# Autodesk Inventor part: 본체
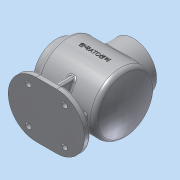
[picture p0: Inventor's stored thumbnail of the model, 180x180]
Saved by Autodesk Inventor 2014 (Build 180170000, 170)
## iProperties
Created: 2023-01
Part Number: 본체
Material: 알루미늄 6061
Document SubType Name: Modeling
Designer: dg
Mass: 1037.87 g
Surface Area: 1159.88 cm^2
Volume: 382.978 cm^3
Density: 2.71 g/cm^3
Appearance: 알루미늄 - 평지
Author: dg
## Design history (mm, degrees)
sketch "스케치1"
  geometry: L1 (0, 0)-(-122, 0); L2 (-122, 0)-(-122, 38); L3 (-122, 38)-(-110, 38); L4 (-110, 38)-(-110, 50); L5 (-110, 50)-(-10.913, 50); A1 r 120 centre (-120, 0) between (0, 0) and (-10.913, 50)
  constraints: 10 end point, 2 perpendicular, 2 point on circle, 1 centre point, 1 horizontal, 1 horizontal alignment, 1 parallel, 1 vertical
  dimensions: "d0" = 120 radius of A1; "d1" = 122 distance of L1.start L1.end; "d9" = 110 horizontal distance of L1.start L4.end; "d10" = 100 diameter of L5 L1; "d11" = 76 diameter of L3 L1
revolve "회전1" sketch "스케치1" stored, may be unused: angle "d3" = 90 deg
node "작업 평면2"
sketch "스케치4"
  geometry: L1 (-122, 38)-(-110, 38) reference; L2 (-122, -38)-(-122, 38) reference; L3 (-122, 0)-(0, 0); L4 (-110, 50)-(-10.913, 50) reference; L5 (-122, 0)-(-122, 27); L6 (-122, 27)-(-105, 27); L7 (-105, 27)-(-105, 45); L8 (-105, 45)-(-14.17, 45); A1 r 120 centre (-120, 0) between (-10.913, -50) and (-10.913, 50) reference; A2 r 115 centre (-120, 0) between (-5, 0) and (-14.17, 45); 2 further points
  constraints: 10 end point, 3 point on circle, 2 midpoint, 2 parallel, 2 perpendicular, 1 centre point, 1 coincident, 1 horizontal, 1 point on line
  dimensions: "d12" = 54 diameter of L6 L3; "d13" = 90 diameter of L8 L3; "d14" = 5 radial gap between concentric circles of A1 A2; "d15" = 17 distance of L5.end L6.end
revolve "회전2" sketch "스케치4" stored, may be unused: angle "d16" = 90 deg
fillet "모깎기1" dims "d19" = 8
fillet "모깎기2" dims "d20" = 3
node "작업 평면5"
node "작업 평면6"
sketch "스케치7"
  geometry: L1 (110, 42)-(110, -42) reference; C1 r 38 at (59, 0); 1 further point
  constraints: 1 centre point, 1 horizontal alignment
  dimensions: "d23" = 51 distance from line of C1.centre L1; "d24" = 76 diameter of C1
extrude "돌출2" join sketch "스케치7" stored distance "d25" = 12; taper "d26" = 0 deg
sketch "스케치8"
  geometry: C1 r 38 at (0, 0) reference; C2 r 27 at (0, 0); 1 further point
  constraints: 1 centre point, 1 coincident
  dimensions: "d27" = 54 diameter of C2
extrude "돌출3" cut sketch "스케치8" stored distance "d28" = 12; taper "d29" = 0 deg
sketch "스케치9" dims "d30" = 65
  geometry: C1 r 27 at (0, 0) reference; C2 r 38 at (0, 0) reference; 3 further points
  constraints: 2 horizontal alignment, 1 coincident, 2 other
hole "구멍1" sketch "스케치9" at (-32.5, 0) diameter "d31" = 3.242; stored, may be unused: countersink angle "d35" = 90 deg, drill point angle "d37" = 118 deg; dims "d32" = 8, "d33" = 4, "d34" = 2, "d36" = 10
chamfer "모따기1" distance "d41" = 1; stored, may be unused: second distance "d42" = 2, angle "d43" = 45 deg
node "작업 평면7"
sketch "스케치10"
  geometry: L1 (76, -46)-(42, -46); L2 (42, 46)-(76, 46); C1 r 38 at (59, 0) reference; A1 r 46 centre (42, 0) between (42, 46) and (42, -46); A2 r 46 centre (76, 0) between (76, -46) and (76, 46); 2 further points
  constraints: 4 end point, 4 point on circle, 4 tangent, 2 centre point, 2 horizontal, 1 horizontal alignment, 1 midpoint, 1 vertical alignment
  dimensions: "d45" = 92 distance between parallel lines of L2 L1; "d46" = 126 dimension on A1 A2
extrude "돌출4" join sketch "스케치10" distance "d47" = 10; taper "d48" = 0 deg
sketch "스케치11"
  geometry: L1 (-42, 46)-(-76, 46) reference; L2 (-54, 35)-(-64, 35); L3 (-64, 35)-(-64, -35); L4 (-64, -35)-(-54, -35); L5 (-54, -35)-(-54, 35); A1 r 46 centre (-76, 0) between (-76, 46) and (-76, -46) reference; 4 further points
  constraints: 8 end point, 3 midpoint, 2 parallel, 1 horizontal, 1 horizontal alignment, 1 perpendicular, 1 vertical alignment
  dimensions: "d50" = 70 distance of L2.end L3.end; "d51" = 10 distance of L2.start L2.end
extrude "돌출5" join sketch "스케치11" stored distance "d52" = 12; taper "d53" = 0 deg
fillet "모깎기3" dims "d54" = 3
node "작업 평면8"
sketch "스케치12"
  geometry: L1 (-29.641, 20)-(-35, 0); L2 (39.641, 20)-(45, 0); L3 (-38, 20)-(47.827, 20) reference; L4 (-55, 0)-(-12, 0) reference; L5 (22, 0)-(65, 0) reference; L6 (0, 0)-(0, 34.293) reference; L7 (10, 0)-(10, 34.293) reference; L8 (-12, 0)-(22, 0) reference; L9 (-58, -10)-(-58, -3) reference; 1 further point
  constraints: 4 end point, 4 point on line
  dimensions: "d57" = 105 deg angle of L4 L1; "d58" = 105 deg angle of L5 L2; "d59" = 80 distance of L2.end L1.end; "d60" = 23 distance from line of L1.end L9
feature "리브1" dims "d61" = 1, "d62" = 10, "d63" = 0, "d64" = 0, "d65" = 1, "d66" = 1
feature "리브2" dims "d67" = 1, "d68" = 10, "d69" = 0, "d70" = 0, "d71" = 1, "d72" = 1
fillet "모깎기4" dims "d73" = 3
fillet "모깎기5" dims "d74" = 3
sketch "스케치13" dims "d75" = 65
  geometry: C1 r 38 at (0, 0) reference; C2 r 27 at (0, 0) reference; 2 further points
  constraints: 2 horizontal alignment, 1 coincident, 2 other
hole "구멍2" sketch "스케치13" at (-32.5, 0) diameter "d76" = 3.242; stored, may be unused: countersink angle "d80" = 90 deg, drill point angle "d82" = 118 deg; dims "d77" = 8, "d78" = 4, "d79" = 2, "d81" = 10
sketch "스케치14"
  geometry: L1 (-57, 38)-(-61, 38) reference; C1 r 4.5 at (-89, 30); C2 r 4.5 at (-29, 30); C3 r 4.5 at (-89, -30); C4 r 4.5 at (-29, -30); A1 r 43 centre (-76, 0) between (-76, 43) and (-76, -43) reference; 2 further points
  constraints: 4 centre point, 3 equal radius, 2 horizontal alignment, 2 vertical alignment, 1 midpoint
  dimensions: "d86" = 60 distance of C2.centre C1.centre; "d87" = 60 distance of C3.centre C1.centre; "d88" = 30 vertical distance of A1.centre C1.centre; "d89" = 30 horizontal distance of point (-59, 38) C1.centre; "d90" = 9 diameter of C1
extrude "돌출6" cut sketch "스케치14" distance "d91" = 12; taper "d92" = 0 deg
node "작업 평면10"
  node "작업 평면9"
sketch "스케치15"
  geometry: L1 (-122, -38)-(-122, 38) reference; L2 (-42, -80)-(4, -80) reference; 2 further points
  constraints: 1 other
  dimensions: "d94" = 63 distance from line of L1 point (-59, 0); "d95" = 80 distance from line of L2 point (-59, 0)
feature "엠보싱1" sketch "스케치15" dims "d0" = 120, "d1" = 122, "d9" = 110, "d10" = 100, "d11" = 76, "d12" = 54, "d13" = 90, "d14" = 5, "d15" = 17, "d51" = 10, "d74" = 3, "d78" = 4, "d96" = 0.5, "d97" = 0
fillet "모깎기6" dims "d98" = 3
node "솔리드1"
pattern_circular "원형 패턴1" dims angle "d39" = 360 deg
pattern_circular "원형 패턴2" dims angle "d84" = 360 deg
node "투영된 루프1"
other parameters: "d22" = 64, "d93" = 104.75
